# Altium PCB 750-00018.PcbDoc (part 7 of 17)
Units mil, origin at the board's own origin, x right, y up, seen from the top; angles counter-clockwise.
Board outline 7086.64 x 6299.21 mil, 8 copper layers (Top Layer, L2, L3, L4, L5, L6, L7, Bottom Layer), stack 60.6 mil thick; 1356 components, 1054 nets, 4851 pads, 4296 vias.
Unrouted connection lines stored in the file: 12.
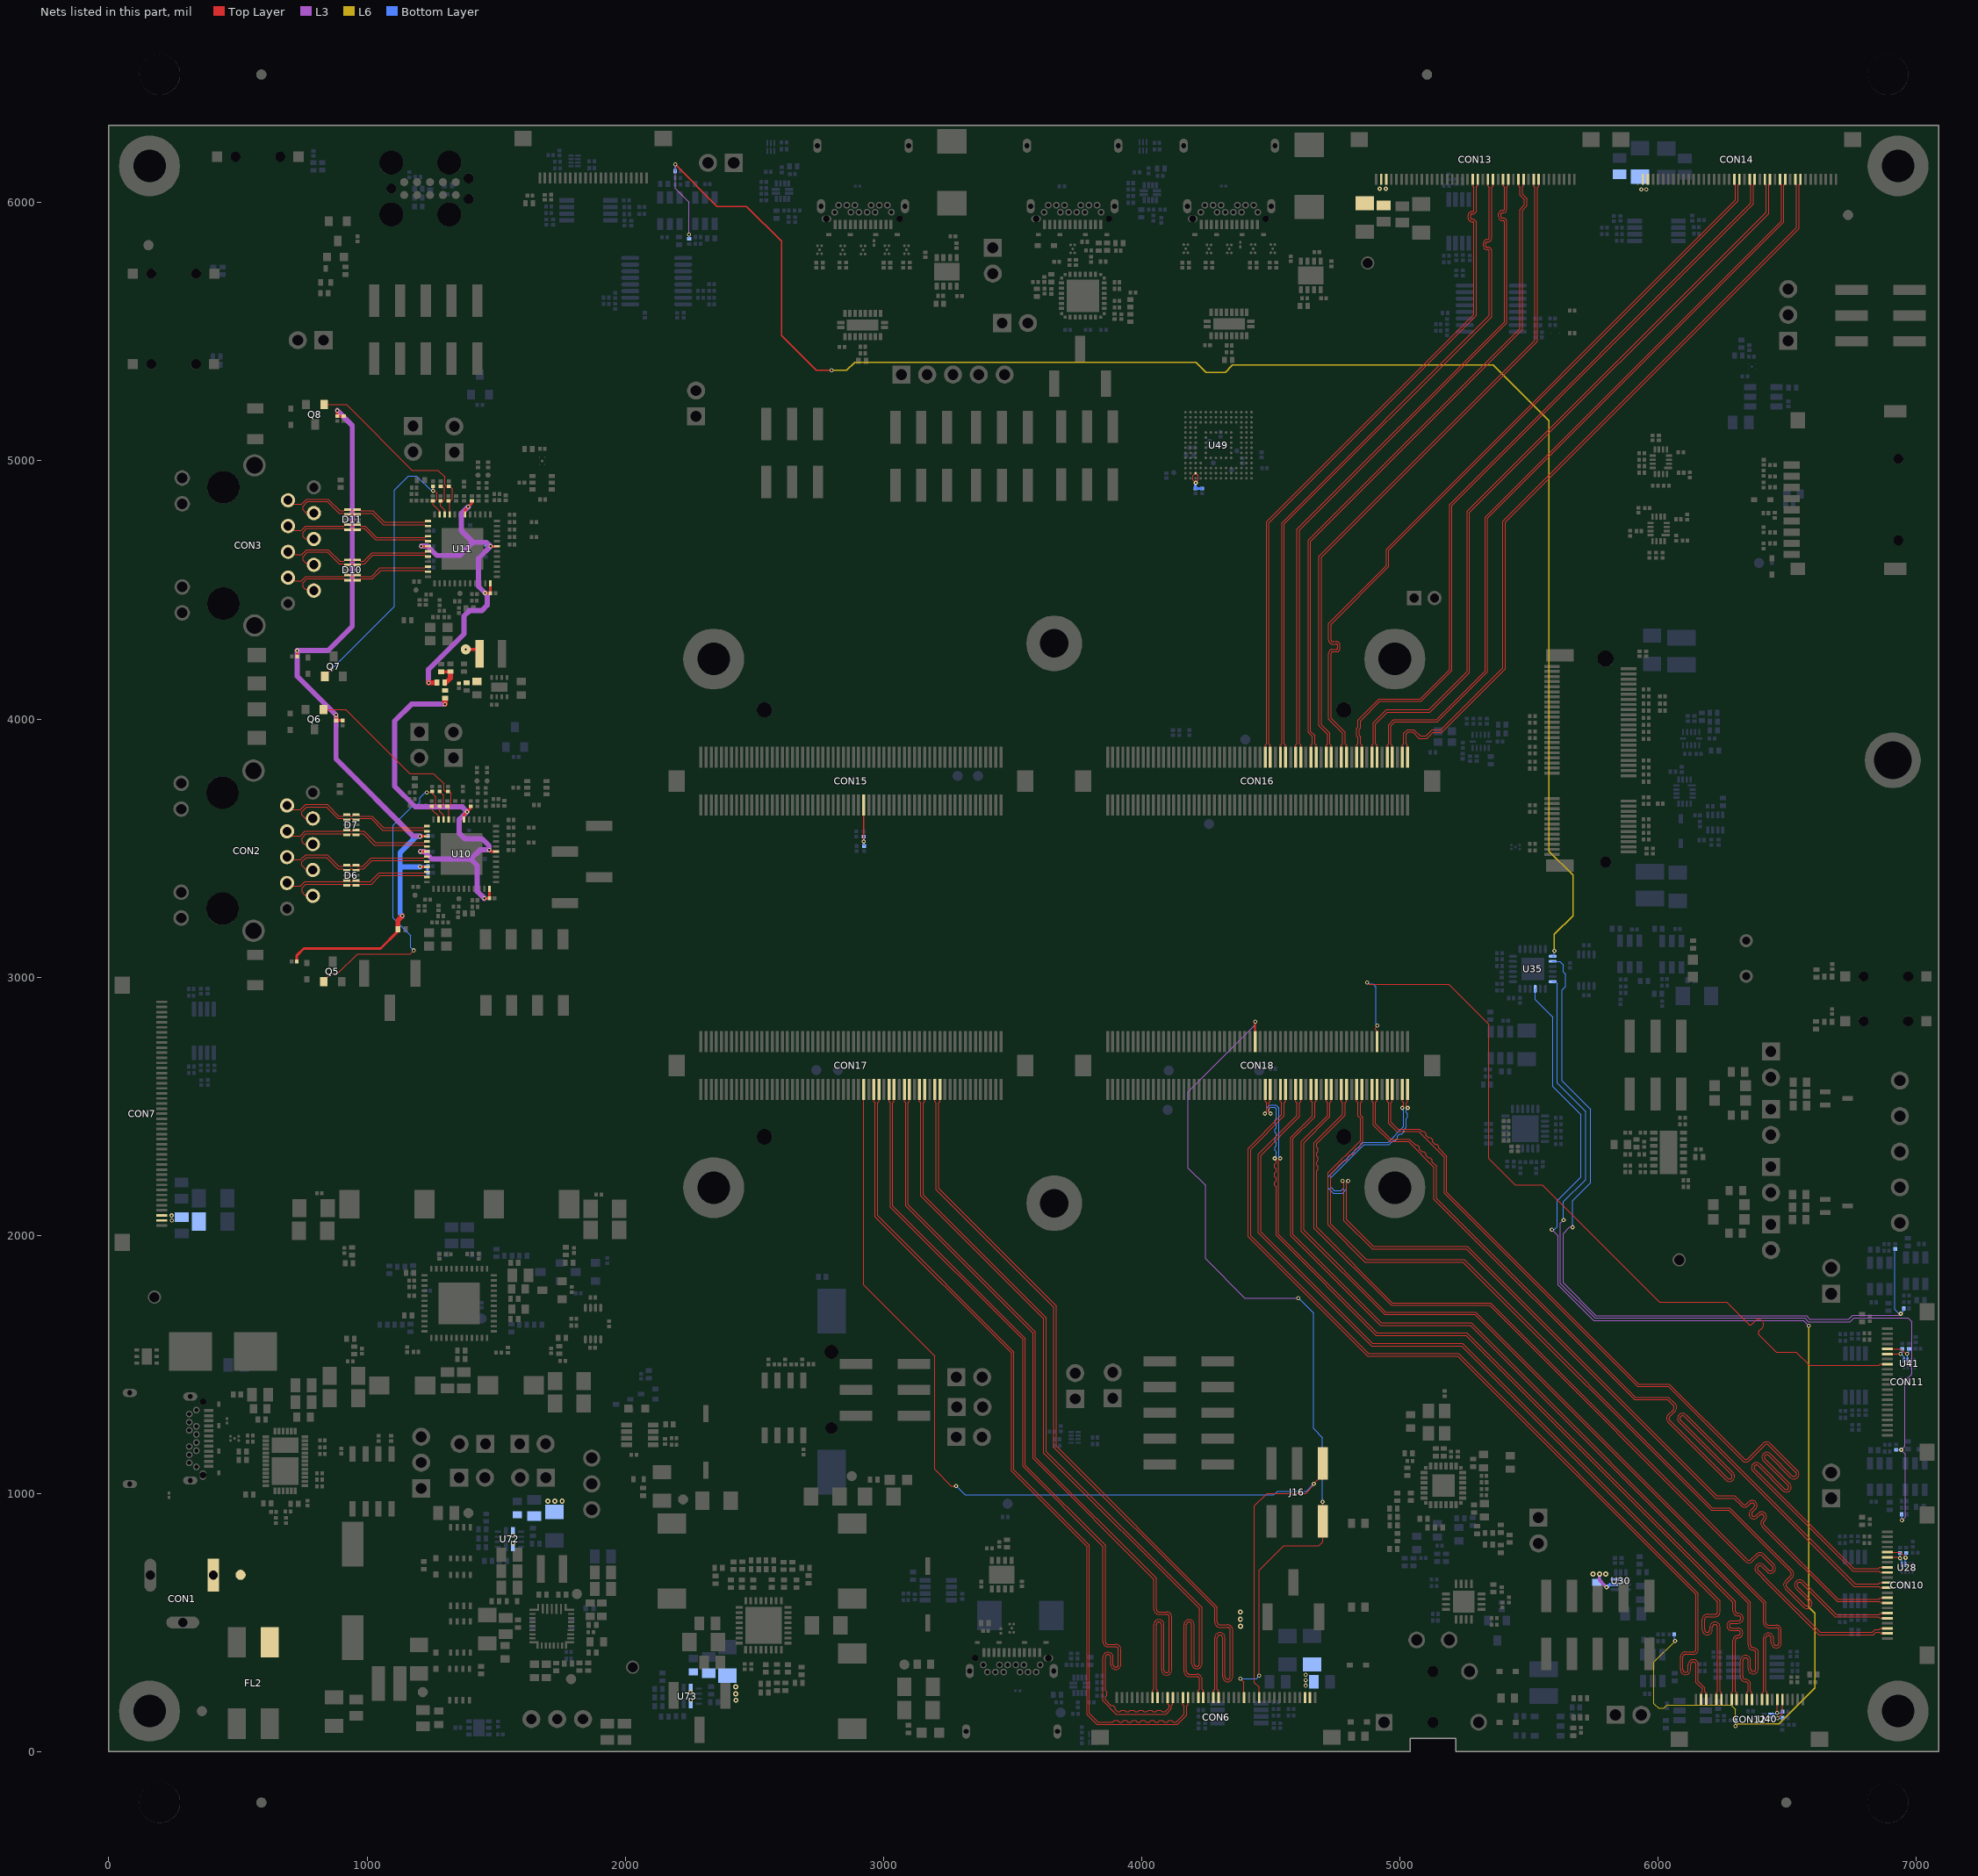
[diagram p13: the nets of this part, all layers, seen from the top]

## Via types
v1: diameter 16, hole 8, Top Layer to Bottom Layer, tented both sides, 3994 vias
v2: diameter 20, hole 10, Top Layer to Bottom Layer, tented both sides, 266 vias
v3: diameter 14, hole 7.87, Top Layer to Bottom Layer, tented both sides, 24 vias
v4: diameter 22, hole 12, Top Layer to Bottom Layer, tented both sides, 8 vias
v5: diameter 24, hole 12, Top Layer to Bottom Layer, tented both sides, 4 vias

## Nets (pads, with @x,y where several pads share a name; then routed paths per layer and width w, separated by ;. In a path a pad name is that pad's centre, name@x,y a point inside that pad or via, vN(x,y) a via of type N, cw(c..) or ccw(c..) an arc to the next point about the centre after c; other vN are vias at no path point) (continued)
CSI_B_DATA3_P: CON11.15 CON18.14 | length 3264
  Top Layer w4: v1(4873.09,2979.63) 4879.51,2973.2 5189.03,2973.2 5344.29,2817.94 5344.29,2297.3 5446.86,2194.73 5551.76,2194.73 6005.26,1741.23 6264.91,1741.23 6345.25,1660.89 6350.02,1656.11 ccw(c6356.74,1662.83) 6363.46,1656.11 6376.06,1668.72 cw(c6389.5,1655.28) 6402.93,1668.72 cw(c6389.5,1655.28) 6402.93,1641.85 6390.33,1629.24 ccw(c6397.05,1622.53) 6390.33,1615.81 6429.57,1576.57 6457.54,1548.6 6534.34,1548.6 6586.88,1496.07 6855.69,1496.07 6860.79,1501.16 CON11.15@6887.83,1501.16 ; CON18.14@4911.42,2750.44 4911.42,2792.84 4906.13,2798.12 4906.13,2803.74 4912.54,2810.15 v1(4912.54,2812.51)
  Bottom Layer w4: v1(4873.09,2979.63) 4879.34,2973.38 4894.84,2973.38 4906.74,2961.48 4906.74,2818.32 v1(4912.54,2812.51)
"CSI_B_GPIO0 / PWR": CON11.17 R386.1 U41.5 | length 106
  Top Layer w4: CON11.17@6887.83,1540.53 6888.17,1540.87 6888.4,1540.64 v1(6938.76,1540.64)
  Bottom Layer w4: R386.1@6946.07,1560.95 6946.87,1560.16 6946.87,1548.75 v1(6938.76,1540.64) 6941.04,1540.64 6952.6,1529.08 U41.5@6952.6,1516.85
"CSI_B_GPIO1 / RST": CON11.18 R385.1 U41.6 | length 135.2
  Top Layer w4: CON11.18@6887.83,1560.22 6941.02,1560.22 6961.36,1539.87 6963.44,1539.87 v1(6964.47,1540.9)
  Bottom Layer w4: U41.6@6966.38,1516.85 6966.38,1539 v1(6964.47,1540.9) 6967.41,1540.9 6970.53,1544.02 6970.53,1559.65 R385.1@6971.83,1560.95
CSI_C_CLOCK_N: CON10.8 CON18.1 | length 3659.9
  Top Layer w4: v1(4777.71,2211.06) 4783.92,2204.86 4783.92,2056.77 4892.85,1947.84 5257.03,1947.84 6223.04,981.83 6292.87,981.83 6317.38,957.32 6322.14,952.56 ccw(c6335.59,965.98) 6349.02,952.55 6357.42,960.95 cw(c6364.14,954.23) 6370.86,960.95 cw(c6364.14,954.23) 6370.86,947.51 ; CON18.1@5029.53,2565.4 5029.53,2517.05 5024.44,2511.96 5024.44,2500.35 v1(5030.67,2494.12) ; 6370.84,947.49 6357.71,934.37 ccw(c6371.15,920.93) 6357.71,907.5 ccw(c6371.15,920.93) 6383.03,906.1 6383.19,906.1 6394.3,917.21 cw(c6401.01,910.49) 6407.73,917.21 cw(c6401.01,910.49) 6407.73,903.77 6402.76,898.81 ccw(c6416.2,885.37) 6402.78,871.92 6424.42,850.29 6693.22,581.48 6856.52,581.48 6861.62,576.39 CON10.8@6887.83,576.39
  Bottom Layer w4: v1(4777.71,2211.06) 4783.87,2204.9 4783.87,2183.68 4773.33,2173.14 4745.67,2173.14 4731.88,2186.93 4731.88,2222.2 4861.39,2351.71 4958.63,2351.71 4974.97,2368.05 4982.75,2368.05 4991.23,2376.53 4991.23,2384.31 4999.72,2392.8 5007.5,2392.8 5015.98,2401.28 5015.98,2409.06 5024.47,2417.55 5024.47,2452.92 5029.97,2458.43 5029.97,2470.43 5024.47,2475.93 5024.47,2487.93 v1(5030.67,2494.12)
CSI_C_CLOCK_P: CON10.9 CON18.3 | length 3661.8
  Top Layer w4: v1(4799.53,2211.06) 4793.42,2204.95 4793.42,2060.71 4896.78,1957.34 5260.97,1957.34 6226.98,991.33 6296.8,991.33 6324.1,964.04 6328.87,959.26 ccw(c6335.59,965.98) 6342.31,959.26 6350.71,967.66 cw(c6364.14,954.23) 6377.58,967.66 cw(c6364.14,954.23) 6378.97,942.35 6378.97,942.19 6364.43,927.65 ccw(c6371.15,920.93) 6364.43,914.21 ccw(c6371.15,920.93) 6377.87,914.21 ; v1(5008.85,2494.12) 5014.94,2500.21 5014.94,2513.4 5009.84,2518.49 CON18.3@5009.84,2565.4 ; 6377.89,914.23 6387.58,923.93 cw(c6401.01,910.49) 6414.45,923.93 cw(c6401.01,910.49) 6414.45,897.06 ; 6414.45,897.06 6409.48,892.09 ccw(c6416.2,885.37) 6409.48,878.65 6431.13,857 6697.15,590.98 6855.27,590.98 6860.36,596.08 CON10.9@6887.83,596.08
  Bottom Layer w4: v1(4799.53,2211.06) 4793.37,2204.9 4793.37,2179.75 4777.26,2163.64 4741.73,2163.64 4722.38,2183 4722.38,2226.13 4857.45,2361.21 4954.69,2361.21 5014.97,2421.48 5014.97,2488 v1(5008.85,2494.12)
CSI_C_DATA0_N: CON10.2 CON18.27 | length 3662
  Top Layer w4: CON18.27@4773.62,2565.4 4773.62,2518.48 4778.72,2513.39 4778.72,2469.6 4667.58,2358.46 4667.58,2027.99 4966.68,1728.89 5347.21,1728.89 6333.33,742.77 6338.09,738 6338.14,737.96 ccw(c6352.06,751.96) 6366,737.96 6387.26,759.23 cw(c6394.49,751.96) 6401.71,759.23 6442.73,718.22 cw(c6435.48,710.97) 6442.73,703.72 cw(c6435.48,710.97) 6428.23,703.72 6408.46,723.5 ccw(c6394.49,709.53) 6380.53,695.57 6425.76,650.33 6434.05,642.04 6623.21,452.88 6833.36,452.88 6843.85,463.37 6857.27,463.37 6862.37,458.28 CON10.2@6887.83,458.28
CSI_C_DATA0_P: CON10.3 CON18.25 | length 3659.9
  Top Layer w4: CON18.25@4793.31,2565.4 4793.31,2518.17 4788.22,2513.08 4788.22,2465.66 4677.08,2354.53 4677.08,2342.53 4682.58,2337.03 4682.58,2325.03 4677.08,2319.52 4677.08,2307.53 4682.58,2302.02 4682.58,2290.02 4677.08,2284.52 4677.08,2272.52 4682.58,2267.02 4682.58,2255.02 4677.08,2249.52 4677.08,2031.93 4970.62,1738.39 5351.14,1738.39 6340.04,749.48 6344.82,744.7 ccw(c6352.06,751.96) 6359.29,744.69 6380.56,765.96 cw(c6394.49,751.96) 6408.42,765.96 6449.45,724.93 cw(c6435.48,710.97) 6449.45,697 cw(c6435.48,710.97) 6421.52,697 6401.74,716.78 ccw(c6394.49,709.53) 6387.24,702.29 6437.39,652.14 6440.77,648.76 6627.14,462.38 6829.42,462.38 6839.91,472.87 6856.55,472.87 6861.64,477.97 CON10.3@6887.83,477.97
CSI_C_DATA1_N: CON10.5 CON18.21 | length 3662
  Top Layer w4: CON18.21@4832.68,2565.4 4832.68,2519.15 4837.77,2514.06 4837.77,2462.69 4846.96,2453.5 4846.96,2367.02 4722.38,2242.44 4722.38,2039.98 4865.47,1896.89 5244.33,1896.89 6206.24,934.98 6273.36,934.98 6507.81,700.53 6512.56,695.78 ; 6512.58,695.76 cw(c6505.33,688.51) 6512.6,681.28 6491.34,660.03 ccw(c6505.33,646.09) 6491.31,632.18 6562.62,560.87 ccw(c6576.59,574.83) 6590.55,560.87 ccw(c6576.59,574.83) 6590.55,588.8 6540.51,638.84 cw(c6547.76,646.09) 6555.01,653.33 6644.79,563.55 6648.18,560.17 6685.91,522.43 6854,522.43 6859.09,517.34 CON10.5@6887.83,517.34
CSI_C_DATA1_P: CON10.6 CON18.19 | length 3659.9
  Top Layer w4: 4823.23,2322.07 4814.75,2313.59 4806.97,2313.59 4798.48,2305.1 4798.48,2297.33 4790,2288.84 4782.22,2288.84 4731.88,2238.5 4731.88,2043.92 4869.41,1906.39 5248.27,1906.39 6210.18,944.48 6277.29,944.48 6514.52,707.25 6519.29,702.48 ; 4823.23,2322.08 4823.23,2329.85 4831.71,2338.34 4839.49,2338.34 4847.98,2346.82 ; 4847.98,2346.82 4847.98,2354.6 4856.46,2363.09 4856.46,2457.43 4847.27,2466.63 4847.27,2513.56 4852.36,2518.65 CON18.19@4852.36,2565.4 ; 6519.32,702.45 cw(c6505.33,688.51) 6519.32,674.57 6498.07,653.32 ccw(c6505.33,646.09) 6498.06,638.87 6569.34,567.58 ccw(c6576.59,574.83) 6583.83,567.58 ccw(c6576.59,574.83) 6583.83,582.08 6533.79,632.12 cw(c6547.76,646.09) 6561.72,660.05 6637.37,584.4 6654.89,566.88 6689.85,531.93 6854.75,531.93 6859.84,537.02 CON10.6@6887.83,537.02
CSI_C_DATA2_N: CON10.11 CON18.15 | length 3662
  Top Layer w4: CON18.15@4891.73,2565.4 4891.73,2519.12 4896.83,2514.03 4896.83,2427.49 4960.94,2363.37 5033.04,2363.37 5132.43,2263.98 5132.43,2139.34 5907.9,1363.87 6035.78,1363.87 6054.48,1345.16 6059.24,1340.41 ; 6059.26,1340.39 cw(c6052.01,1333.14) 6059.28,1325.91 6038.02,1304.65 ccw(c6052.01,1290.72) 6038.02,1276.78 6262.3,1052.49 ccw(c6276.27,1066.46) 6290.23,1052.49 ccw(c6276.27,1066.46) 6290.23,1080.42 6087.19,1283.47 cw(c6094.44,1290.72) 6101.68,1297.96 6370.29,1029.35 6759.11,640.54 6855.13,640.54 6860.23,635.45 CON10.11@6887.83,635.45
CSI_C_DATA2_P: CON10.12 CON18.13 | length 3659.9
  Top Layer w4: CON18.13@4911.42,2565.4 4911.42,2520.14 4906.33,2515.04 4906.33,2431.43 4964.88,2372.87 5036.97,2372.87 5059.86,2349.98 5067.64,2349.98 5076.13,2341.5 5076.13,2333.72 5084.61,2325.23 5092.39,2325.23 5100.88,2316.75 5100.88,2308.97 5109.36,2300.49 5117.14,2300.49 5125.62,2292 5125.62,2284.22 5141.93,2267.92 5141.93,2143.27 5911.83,1373.37 6039.71,1373.37 6061.2,1351.88 6065.97,1347.11 cw(c6052.01,1333.14) 6066,1319.2 6044.74,1297.94 ccw(c6052.01,1290.72) 6044.74,1283.49 6269.02,1059.21 ccw(c6276.27,1066.46) 6283.52,1059.21 ccw(c6276.27,1066.46) 6283.52,1073.7 6080.47,1276.75 cw(c6094.44,1290.72) 6108.4,1304.68 6377.01,1036.07 6763.04,650.04 6854.34,650.04 6859.44,655.13 CON10.12@6887.83,655.13
CSI_C_DATA3_N: CON10.14 CON18.9 | length 3661.8
  Top Layer w4: CON18.9@4950.79,2565.4 4950.79,2518.71 4955.88,2513.61 4955.88,2434.25 4987.83,2402.3 5072.34,2402.3 5171.88,2302.76 5171.88,2162.82 5919.99,1414.71 6039.47,1414.71 6321.94,1132.24 6326.71,1127.48 6326.76,1127.43 ccw(c6340.15,1140.91) 6326.93,1127.25 ccw(c6340.15,1140.9) 6353.58,1127.46 6414.05,1187.93 cw(c6420.76,1181.21) 6427.47,1187.93 6533.01,1082.39 cw(c6526.29,1075.67) 6519.58,1068.96 6434.2,1154.34 ccw(c6420.76,1140.9) 6407.33,1127.47 6503.36,1031.44 cw(c6496.64,1024.72) 6503.36,1018 cw(c6496.64,1024.72) 6489.92,1018 6393.88,1114.04 ccw(c6380.46,1100.6) 6367.01,1114.03 ccw(c6380.46,1100.6) 6367.02,1087.16 6477.9,976.28 6754.59,699.59 6855.19,699.59 6860.29,694.5 CON10.14@6887.83,694.5
CSI_C_DATA3_P: CON10.15 CON18.7 | length 3659.7
  Top Layer w4: CON18.7@4970.47,2565.4 4970.47,2518.5 4965.38,2513.4 4965.38,2438.19 4991.76,2411.8 5076.28,2411.8 5084.76,2403.32 5092.54,2403.32 5101.03,2394.84 5101.03,2387.06 5109.51,2378.57 5117.29,2378.57 5125.78,2370.09 5125.78,2362.31 5134.26,2353.82 5142.04,2353.82 5150.53,2345.34 5150.53,2337.56 5181.38,2306.7 5181.38,2166.76 5923.92,1424.21 6043.4,1424.21 6328.66,1138.96 6333.44,1134.18 ; 6333.46,1134.16 ccw(c6340.15,1140.91) 6333.54,1134.08 ccw(c6340.15,1140.9) 6346.87,1134.18 6407.33,1194.65 cw(c6420.76,1181.21) 6434.19,1194.65 6539.73,1089.11 cw(c6526.29,1075.67) 6512.86,1062.24 6427.48,1147.62 ccw(c6420.76,1140.9) 6414.04,1134.19 6510.08,1038.15 cw(c6496.64,1024.72) 6510.08,1011.28 cw(c6496.64,1024.72) 6483.21,1011.28 6387.17,1107.32 ccw(c6380.46,1100.6) 6373.74,1107.31 ccw(c6380.46,1100.6) 6373.74,1093.88 6484.62,983 6758.52,709.09 6853.56,709.09 6858.65,714.19 CON10.15@6887.83,714.19
"CSI_C_GPIO0 / PWR": CON10.17 R360.1 U28.5 | length 97.9
  Top Layer w4: CON10.17@6887.83,753.56 6932.8,753.56 v1(6936.76,749.6)
  Bottom Layer w4: R360.1@6936.52,770.29 6936.52,749.84 v1(6936.76,749.6) 6944.03,742.33 U28.5@6944.03,726.08
"CSI_C_GPIO1 / RST": CON10.18 R359.1 U28.6 | length 125.5
  Top Layer w4: CON10.18@6887.83,773.24 6936.88,773.24 v1(6958.5,751.62)
  Bottom Layer w4: U28.6@6957.81,726.08 6957.81,750.93 v1(6958.5,751.62) 6961.41,754.53 R359.1@6961.41,770.45
CSI_D_CLOCK_N: CON12.8 CON18.55 | length 3532.1
  Top Layer w4: CON18.55@4498.03,2565.4 4498.03,2518.99 4492.94,2513.9 4492.94,2478.07 v1(4499.23,2471.78) ; v1(4515.23,2298.56) 4520.64,2293.15 4520.64,2281.15 4515.14,2275.65 4515.14,2263.65 4520.64,2258.15 4520.64,2246.15 4515.14,2240.65 4515.14,2228.65 4520.64,2223.15 4520.64,2211.15 4515.14,2205.64 4515.14,2193.65 4520.64,2188.14 4520.64,1999.61 4907.46,1612.79 5255.9,1612.79 6289.8,578.89 6289.8,552.25 6289.8,545.5 ccw(c6308.8,545.5) 6308.8,526.5 6310.45,526.5 cw(c6310.45,517) 6310.45,507.5 6285.04,507.5 ccw(c6285.04,488.5) 6285.04,469.5 6308.8,469.5 cw(c6308.8,460) 6308.8,450.5 ccw(c6308.8,431.5) 6289.8,431.5 6289.8,383.66 6289.8,234.73 6284.4,229.33 CON12.8@6284.4,202.02
  Bottom Layer w4: v1(4499.23,2471.78) 4493.07,2477.94 4493.07,2489.88 4499.15,2495.96 4514.97,2495.96 4521.81,2489.11 4521.81,2451.59 4516.31,2446.09 4516.31,2434.09 4521.81,2428.59 4521.81,2416.59 4516.31,2411.09 4516.31,2399.09 4521.81,2393.59 4521.81,2381.59 4516.31,2376.09 4516.31,2364.09 4521.81,2358.58 4521.81,2346.58 4516.31,2341.08 4516.31,2329.08 4521.81,2323.58 4521.81,2305.15 v1(4515.23,2298.56)
CSI_D_CLOCK_P: CON12.9 CON18.57 | length 3531.6
  Top Layer w4: v1(4477.42,2471.78) 4483.44,2477.8 4483.44,2514.2 4478.35,2519.29 CON18.57@4478.35,2565.4 ; v1(4537.05,2298.56) 4530.14,2291.66 4530.14,2003.55 4911.4,1622.29 5259.83,1622.29 6299.3,582.83 6299.3,552.25 6299.3,545.5 ccw(c6308.8,545.5) 6308.8,536 6310.45,536 cw(c6310.45,517) 6310.45,498 6285.04,498 ccw(c6285.04,488.5) 6285.04,479 6308.8,479 cw(c6308.8,460) 6308.8,441 ccw(c6308.8,431.5) 6299.3,431.5 6299.3,383.66 6299.3,233.98 6304.08,229.2 CON12.9@6304.08,202.02
  Bottom Layer w4: v1(4477.42,2471.78) 4483.57,2477.94 4483.57,2493.82 4495.21,2505.46 4518.9,2505.46 4531.31,2493.05 4531.31,2304.3 v1(4537.05,2298.56)
CSI_D_DATA0_N: CON12.2 CON18.51 | length 3533
  Top Layer w4: CON18.51@4537.4,2565.4 4537.4,2517.95 4542.49,2512.86 4542.49,2467.38 4412.42,2337.31 4412.42,1994.34 4874.22,1532.54 5222.66,1532.54 6146.32,608.87 6146.32,403.92 6146.32,397.17 cw(c6136.07,397.17) 6136.07,386.92 6106.07,386.92 ccw(c6106.07,367.17) 6086.32,367.17 6086.32,318.44 ccw(c6106.07,318.44) 6125.82,318.44 6125.82,337.17 cw(c6136.07,337.17) 6146.32,337.17 6146.32,272.91 6146.32,268.28 6171.38,243.22 6171.38,234.33 6166.29,229.23 CON12.2@6166.29,202.02
CSI_D_DATA0_P: CON12.3 CON18.49 | length 3533
  Top Layer w4: CON18.49@4557.09,2565.4 4557.09,2518.39 4551.99,2513.3 4551.99,2463.45 4421.92,2333.37 4421.92,1998.27 4878.15,1542.04 5226.59,1542.04 6155.82,612.81 6155.82,403.92 6155.82,397.17 cw(c6136.07,397.17) 6136.07,377.42 6106.07,377.42 ccw(c6106.07,367.17) 6095.82,367.17 6095.82,318.44 ccw(c6106.07,318.44) 6116.32,318.44 6116.32,337.17 cw(c6136.07,337.17) 6155.82,337.17 6155.82,272.91 6155.82,272.21 6180.88,247.15 6180.88,234.08 6185.97,228.98 CON12.3@6185.97,202.02
CSI_D_DATA1_N: CON12.5 CON18.45 | length 3532.1
  Top Layer w4: CON18.45@4596.46,2565.4 4596.46,2518.98 4601.55,2513.89 4601.55,2463.86 4451.45,2313.75 4451.45,2010.5 4890.38,1571.57 5238.82,1571.57 6230.43,579.95 6230.43,549.39 6230.43,542.64 cw(c6220.18,542.64) 6220.18,532.39 6190.18,532.39 ccw(c6190.18,512.64) 6170.43,512.64 6170.43,472.65 ccw(c6190.18,472.65) 6209.93,472.65 6209.93,482.64 cw(c6220.18,482.64) 6230.43,482.64 6230.43,396.74 6230.43,232.87 6225.34,227.77 CON12.5@6225.34,202.02
CSI_D_DATA1_P: CON12.6 CON18.43 | length 3532.1
  Top Layer w4: CON18.43@4616.14,2565.4 4616.14,2518.39 4611.05,2513.29 4611.05,2459.92 4460.95,2309.82 4460.95,2014.44 4894.32,1581.07 5242.76,1581.07 6239.93,583.89 6239.93,549.39 6239.93,542.64 cw(c6220.18,542.64) 6220.18,522.89 6190.18,522.89 ccw(c6190.18,512.64) 6179.93,512.64 6179.93,472.65 ccw(c6190.18,472.65) 6200.43,472.65 6200.43,482.64 cw(c6220.18,482.64) 6239.93,482.64 6239.93,396.74 6239.93,233.15 6245.03,228.06 CON12.6@6245.03,202.02
CSI_D_DATA2_N: CON12.11 CON18.39 | length 3532.1
  Top Layer w4: CON18.39@4655.51,2565.4 4655.51,2519.56 4660.6,2514.47 4660.6,2463.19 4577.05,2379.64 4577.05,1998.75 4923.73,1652.07 5272.17,1652.07 6348.54,575.69 6348.54,419.88 6348.54,413.13 ccw(c6368.29,413.13) 6368.29,393.38 cw(c6368.29,383.13) 6378.54,383.13 6378.54,321.38 cw(c6368.29,321.38) 6358.04,321.38 6358.04,353.13 ccw(c6338.29,353.13) 6318.54,353.13 6318.54,290.8 ccw(c6338.29,290.8) 6338.29,271.05 cw(c6338.29,260.8) 6348.54,260.8 6348.54,254.05 6348.54,235.5 6343.45,230.41 CON12.11@6343.45,202.02
CSI_D_DATA2_P: CON12.12 CON18.37 | length 3532.1
  Top Layer w4: CON18.37@4675.2,2565.4 4675.2,2519.8 4670.1,2514.71 4670.1,2459.26 4586.55,2375.7 4586.55,2002.69 4927.67,1661.57 5276.1,1661.57 6358.04,579.63 6358.04,419.88 6358.04,413.13 ccw(c6368.29,413.13) 6368.29,402.88 cw(c6368.29,383.13) 6388.04,383.13 6388.04,321.38 cw(c6368.29,321.38) 6348.54,321.38 6348.54,353.13 ccw(c6338.29,353.13) 6328.04,353.13 6328.04,290.8 ccw(c6338.29,290.8) 6338.29,280.55 cw(c6338.29,260.8) 6358.04,260.8 6358.04,254.05 6358.04,235 6363.14,229.91 CON12.12@6363.14,202.02
CSI_D_DATA3_N: CON12.14 CON18.33 | length 3533
  Top Layer w4: CON18.33@4714.57,2565.4 4714.57,2518.25 4719.66,2513.16 4719.66,2464.66 4618.21,2363.21 4618.21,2015.8 4940.78,1693.23 5289.22,1693.23 6407.6,574.85 6407.6,507.2 6407.6,500.45 ccw(c6427.35,500.45) 6427.35,480.7 6457.35,480.7 cw(c6457.35,470.45) 6467.6,470.45 6467.6,422.1 cw(c6457.35,422.1) 6447.1,422.1 6447.1,440.45 ccw(c6427.35,440.45) 6407.6,440.45 6407.6,330.79 6407.6,234.28 6402.51,229.19 CON12.14@6402.51,202.02
CSI_D_DATA3_P: CON12.15 CON18.31 | length 3533
  Top Layer w4: CON18.31@4734.25,2565.4 4734.25,2518.62 4729.16,2513.52 4729.16,2460.73 4627.71,2359.28 4627.71,2019.74 4944.72,1702.73 5293.15,1702.73 6417.1,578.79 6417.1,507.2 6417.1,500.45 ccw(c6427.35,500.45) 6427.35,490.2 6457.35,490.2 cw(c6457.35,470.45) 6477.1,470.45 6477.1,422.1 cw(c6457.35,422.1) 6437.6,422.1 6437.6,440.45 ccw(c6427.35,440.45) 6417.1,440.45 6417.1,330.79 6417.1,235.15 6422.19,230.06 CON12.15@6422.19,202.02
"CSI_D_GPIO0 / PWR": CON12.17 R384.1 U40.5 | length 100.6
  Top Layer w4: v1(6461.18,150.34) 6461.56,150.72 CON12.17@6461.56,202.02
  Bottom Layer w4: U40.5@6437.04,147.25 6458.1,147.25 v1(6461.18,150.34) 6476.78,150.34 R384.1@6482.28,155.85
"CSI_D_GPIO1 / RST": CON12.18 R383.1 U40.6 | length 126.9
  Top Layer w4: v1(6463.16,129.84) 6481.25,147.93 CON12.18@6481.25,202.02
  Bottom Layer w4: U40.6@6437.04,133.47 6459.53,133.47 v1(6463.16,129.84) 6481.13,129.84 6481.21,129.77 R383.1@6482.28,130.84
CSI_HV: C292.2 C419.1 C420.1 R603.1 U30.5 U30.6 U72.1 U72.8 | length 97.1
  L3 w12: v2(5772.95,688.34) 5772.95,664.85 v1(5800.27,637.53)
  Bottom Layer w12: v1(5800.27,637.53) 5802.32,637.53 5813.1,648.32 U30.5@5830.82,648.32
  other v1: 1564.85,807.65 1564.85,839.15
  other v2: 4382.85,485.73 4382.08,513.51 4381.88,541.3 5747.49,688.44 5796.93,688.34 1699.85,970.13 1727.64,970.13 1755.42,970.13
CSI_PWR_control_A: R577.1 R583.1 U35.7 | length 6541.2
  Top Layer w5: v1(2193.81,6147.64) 2355.8,5985.66 2470.01,5985.66 2605.64,5850.03 2605.64,5484.79 2739.35,5351.08 v1(2799.29,5351.08)
  L3 w4: v1(2193.81,6147.64) 2193.81,6054.44 2246.62,6001.64 v1(2246.62,5876.21)
  L6 w5: v1(2799.29,5351.08) 2857.58,5351.08 2888.5,5382 4210.17,5382 4249.4,5342.77 4323.96,5342.77 4352.01,5370.83 5361.18,5370.83 5576.77,5155.24 5576.77,3488.38 5669.75,3395.4 5669.75,3238.43 5598.01,3166.69 v1(5598.01,3101.87)
  Bottom Layer w4: v1(2246.62,5876.21) 2246.62,5860.39 R577.1@2247.45,5859.56 ; U35.7@5591.4,3081.08 5595.87,3081.08 5598.01,3083.22 v1(5598.01,3101.87)
  Bottom Layer w5: R583.1@2193.52,6121.5 2193.52,6147.36 v1(2193.81,6147.64)
CSI_PWR_control_B: R590.1 R595.1 U35.8 | length 3048.7
  L3 w4: v1(5668.72,2031.55) 5656.89,2031.55 5632.67,2007.33 5632.67,1815.85 5759.69,1688.83 6574.09,1688.83 6587.2,1675.72 6738.93,1675.72 6753.63,1690.41 6933.23,1690.41 v1(6939.5,1696.68)
  Bottom Layer w4: U35.8@5591.4,3061.4 5619.14,3061.4 5632.64,3047.89 5632.64,3019.57 5640.82,3011.39 5640.82,2963.61 5628.31,2951.1 5628.31,2598.76 5738.99,2488.08 5738.99,2203.99 5668.72,2133.72 v1(5668.72,2031.55) ; R590.1@6918.63,1947.32 6915.93,1944.62 6915.93,1713.22 6932.46,1696.68 v1(6939.5,1696.68) 6951.69,1708.88 R595.1@6951.69,1716.89
CSI_PWR_control_C: R579.1 R585.1 U35.12 | length 3545.2
  L3 w4: v1(5633.95,2059.7) 5622.02,2047.77 5622.02,1813.18 5755.47,1679.73 6568.23,1679.73 6582.19,1665.76 6742.56,1665.76 6758.05,1681.25 6966.88,1681.25 6983.11,1665.02 6983.11,1462.57 6956.13,1435.59 6956.13,1184.32 v1(6941.18,1169.37) 6956.98,1153.57 6956.98,908.8 v1(6944.43,896.24)
  Bottom Layer w4: U35.12@5591.4,2982.66 5601.24,2982.66 5608.69,2975.2 5608.69,2589.48 5719.13,2479.03 5719.13,2216.6 5633.95,2131.41 v1(5633.95,2059.7) ; R579.1@6921.76,1169.89 6940.66,1169.89 v1(6941.18,1169.37) ; R585.1@6943.48,919.84 6943.48,897.19 v1(6944.43,896.24)
CSI_PWR_control_D: R589.1 R596.1 U35.15 | length 4826.2
  L3 w4: v1(5588.34,2022.23) 5612.6,1997.97 5612.6,1807.08 5750.19,1669.49 6563.26,1669.49 v1(6583.06,1649.69)
  L6 w4: v1(6065.87,429.3) 5983.58,347.02 5983.58,186.42 6001.22,168.78 6022.67,168.78 6034.54,180.66 6283.26,180.66 6299.56,164.35 v1(6299.56,98.89)
  L6 w5: v1(6299.56,98.89) 6308.67,108 6467.92,108 6606.54,246.62 6606.54,535.96 6583.18,559.31 6583.06,559.43 v1(6583.06,1649.69)
  Bottom Layer w4: U35.15@5524.23,2954.86 5524.23,2912.52 5591.56,2845.19 5591.56,2577.02 5701.43,2467.15 5701.43,2226.53 5609.89,2134.99 5609.89,2034.29 5597.83,2022.23 v1(5588.34,2022.23) ; R589.1@6062.82,454.52 6062.82,432.35 v1(6065.87,429.3)
  Bottom Layer w5: v1(6299.56,98.89) R596.1@6299.55,121.02
DCJACK12V: CON1.1 FL2.1 TP8.1
DEBUG_EN: CON15.66 R221.1 R607.1 | length 178.3
  Top Layer w5: v1(2923.23,3525.94) CON15.66@2923.23,3666.88
  Bottom Layer w5: R607.1@2923.38,3544.75 2923.38,3526.09 v1(2923.23,3525.94) 2924.61,3524.56 R221.1@2924.61,3508
DP_HV: C217.1 C218.1 C381.1 C382.1 C383.1 C384.1 C385.1 C386.1 C421.1 C422.1 CON6.38 CON6.39 CON7.43 CON7.44 CON13.38 CON13.39 CON14.38 CON14.39 R605.1 U73.1 U73.8
  other v1: 2253.9,199.69 2253.9,231.19 4635.08,256.35 4634.87,277.3 4635.49,298.55 243.55,2057.47 243.2,2077.11 5934.69,6050.74 5954.02,6050.96 4921.72,6053.62 4945.38,6053.93
  other v2: 2428.47,199.73 2427.89,223.86 2428.2,251.48
"DSI_ A_BL_PWM / LVDS_A_BL_PWM / PWM_0": CON6.26 CON18.62 J16.5 | length 3396.8
  Top Layer w4: v1(4381.65,283.46) 4396.07,269.03 CON6.26@4396.07,209.68 ; v1(4455.29,294.78) 4455.29,702.84 4550.31,797.87 4686.27,797.87 4701.95,813.55 J16.5@4701.95,892.47 4701.95,966.37 v1(4700.58,967.74)
  Top Layer w6: CON18.62@4438.98,2750.44 v1@4438.98,2827.49
  L3 w4: v1(4439.84,2828.35) 4439.84,2816.43 4180.13,2556.73 4180.13,2259.79 4246.85,2193.08 4246.85,1909.36 4398.87,1757.34 v1(4606.37,1757.34)
  Bottom Layer w4: v1(4381.65,283.46) 4443.97,283.46 v1(4455.29,294.78) ; v1(4606.37,1757.34) 4608.07,1757.34 4665.61,1699.81 4665.61,1251.25 4700.58,1216.27 v1(4700.58,967.74)
"DSI_A_CLOCK_N / LVDS_A_CLK_N": CON6.8 CON17.39 | length 3249.9
  Top Layer w4: CON17.39@3080.71,2565.4 3080.71,2517.77 3085.65,2512.83 3085.65,2114.52 3578.75,1621.42 3578.75,1136.01 4046.83,667.93 4046.83,558.8 4046.83,552.05 ccw(c4066.58,552.05) 4066.58,532.3 4096.58,532.3 cw(c4096.58,522.05) 4106.83,522.05 4106.83,316.8 cw(c4096.58,316.8) 4086.33,316.8 4086.33,492.05 ccw(c4066.58,492.05) 4046.83,492.05 4046.83,290.39 4046.83,242.91 4041.74,237.82 CON6.8@4041.74,209.68
"DSI_A_CLOCK_P / LVDS_A_CLK_P": CON6.9 CON17.37 | length 3250
  Top Layer w4: CON17.37@3100.4,2565.4 3100.4,2518.01 3095.15,2512.76 3095.15,2118.46 3588.25,1625.36 3588.25,1139.95 4056.33,671.87 4056.33,558.8 4056.33,552.05 ccw(c4066.58,552.05) 4066.58,541.8 4096.58,541.8 cw(c4096.58,522.05) 4116.33,522.05 4116.33,316.8 cw(c4096.58,316.8) 4076.83,316.8 4076.83,492.05 ccw(c4066.58,492.05) 4056.33,492.05 4056.33,290.39 4056.33,242.66 4061.42,237.56 CON6.9@4061.43,209.68
"DSI_A_DATA0_N / LVDS_A_LANE0_N": CON6.20 CON17.27 | length 3250
  Top Layer w4: CON17.27@3198.82,2565.4 3198.82,2517.77 3204.05,2512.54 3204.05,2177.17 3659.58,1721.63 3659.58,1179.44 4283.05,555.97 4283.05,508.65 4283.05,501.9 ccw(c4302.8,501.9) 4302.8,482.15 4332.8,482.15 cw(c4332.8,471.9) 4343.05,471.9 4343.05,291.05 cw(c4332.8,291.05) 4322.55,291.05 4322.55,441.9 ccw(c4302.8,441.9) 4283.05,441.9 4283.05,263.28 4283.05,242.25 4277.96,237.16 CON6.20@4277.96,209.68
"DSI_A_DATA0_P / LVDS_A_LANE0_P": CON6.21 CON17.25 | length 3249.9
  Top Layer w4: CON17.25@3218.51,2565.4 3218.51,2518.01 3213.55,2513.05 3213.55,2181.1 3669.08,1725.57 3669.08,1183.37 4292.55,559.9 4292.55,508.65 4292.55,501.9 ccw(c4302.8,501.9) 4302.8,491.65 4332.8,491.65 cw(c4332.8,471.9) 4352.55,471.9 4352.55,291.05 cw(c4332.8,291.05) 4313.05,291.05 4313.05,441.9 ccw(c4302.8,441.9) 4292.55,441.9 4292.55,263.28 4292.55,242 4297.65,236.91 CON6.21@4297.65,209.68
"DSI_A_DATA1_N / LVDS_A_LANE1_N": CON6.17 CON17.33 | length 3250
  Top Layer w4: CON17.33@3139.77,2565.4 3139.77,2517.77 3144.84,2512.69 3144.84,2152.86 3621.07,1676.63 3621.07,1157.56 4224,554.63 4224,540.34 4224,341.07 cw(c4213.75,341.07) 4203.5,341.07 4203.5,491.91 ccw(c4183.75,491.91) 4164,491.91 4164,311.07 ccw(c4183.75,311.07) 4183.75,291.32 4213.75,291.32 cw(c4213.75,281.07) 4224,281.07 4224,274.32 4224,242.53 4218.91,237.44 CON6.17@4218.91,209.68
"DSI_A_DATA1_P / LVDS_A_LANE1_P": CON6.18 CON17.31 | length 3250
  Top Layer w4: CON17.31@3159.45,2565.4 3159.45,2518.01 3154.34,2512.9 3154.34,2156.79 3630.57,1680.57 3630.57,1161.5 4233.5,558.57 4233.5,540.34 4233.5,341.07 cw(c4213.75,341.07) 4194,341.07 4194,491.91 ccw(c4183.75,491.91) 4173.5,491.91 4173.5,311.07 ccw(c4183.75,311.07) 4183.75,300.82 4213.75,300.82 cw(c4213.75,281.07) 4233.5,281.07 4233.5,274.32 4233.5,242.61 4238.59,237.52 CON6.18@4238.59,209.68
"DSI_A_DATA2_N / LVDS_A_LANE2_N": CON6.14 CON17.49 | length 3250.4
  Top Layer w4: CON17.49@2982.29,2565.4 2982.29,2518.01 2977.14,2512.86 2977.14,2076.01 3505.11,1548.04 3505.11,1091.72 3797.84,798.99 3797.84,147.93 3830.34,115.43 3889.31,115.43 3894.81,120.93 3906.81,120.93 3912.32,115.43 3924.32,115.43 3929.82,120.93 3941.82,120.93 3947.32,115.43 3959.32,115.43 3964.82,120.93 3976.82,120.93 3982.32,115.43 3994.32,115.43 3999.82,120.93 4011.82,120.93 4017.32,115.43 4029.32,115.43 4034.82,120.93 4046.82,120.93 4052.32,115.43 4064.32,115.43 4069.82,120.93 4081.82,120.93 4087.32,115.43 4099.32,115.43 4104.82,120.93 4116.82,120.93 4122.32,115.43 4134.32,115.43 4164.94,146.05 4164.94,177.87 4159.85,182.97 CON6.14@4159.85,209.68
"DSI_A_DATA2_P / LVDS_A_LANE2_P": CON6.15 CON17.51 | length 3250
  Top Layer w4: CON17.51@2962.6,2565.4 2962.6,2517.77 2967.64,2512.73 2967.64,2072.07 3495.61,1544.11 3495.61,1087.79 3788.34,795.05 3788.34,143.99 3826.41,105.93 3874.1,105.93 4138.26,105.93 4174.44,142.11 4174.44,177.76 4179.54,182.85 CON6.15@4179.54,209.68
"DSI_A_DATA3_N / LVDS_A_LANE3_N": CON6.11 CON17.43 | length 3250
  Top Layer w4: CON17.43@3041.34,2565.4 3041.34,2518.01 3036.16,2512.82 3036.16,2113.33 3210.54,1938.94 3549.11,1600.37 3549.11,1109.47 3859.22,799.37 3859.22,432.78 3859.22,426.03 ccw(c3869.47,426.03) 3869.47,415.78 3899.47,415.78 cw(c3899.47,396.03) 3919.22,396.03 3919.22,338 cw(c3899.47,338) 3879.72,338 3879.72,366.03 ccw(c3869.47,366.03) 3859.22,366.03 3859.22,311.62 3859.22,236.27 3864.72,230.77 3864.72,218.77 3859.22,213.27 3859.22,201.27 3880.63,179.86 3888.41,179.86 3896.9,171.37 3896.9,163.6 3905.38,155.11 3915.48,155.11 3920.98,160.61 3932.98,160.61 3938.48,155.11 3950.48,155.11 3955.98,160.61 3967.98,160.61 3973.48,155.11 3985.48,155.11 3990.98,160.61 4002.98,160.61 4008.48,155.11 4020.48,155.11 4025.98,160.61 4037.98,160.61 4043.49,155.11 4055.49,155.11 4060.99,160.61 4072.99,160.61 4078.49,155.11 4090.49,155.11 4105.89,170.51 4105.89,178.91 4100.8,184 CON6.11@4100.8,209.68
"DSI_A_DATA3_P / LVDS_A_LANE3_P": CON6.12 CON17.45 | length 3249.5
  Top Layer w4: CON17.45@3021.66,2565.4 3021.66,2517.77 3026.66,2512.77 3026.66,2109.39 3539.61,1596.44 3539.61,1105.54 3849.72,795.43 3849.72,432.78 3849.72,426.03 ccw(c3869.47,426.03) 3869.47,406.28 3899.47,406.28 cw(c3899.47,396.03) 3909.72,396.03 3909.72,338 cw(c3899.47,338) 3889.22,338 3889.22,366.03 ccw(c3869.47,366.03) 3849.72,366.03 3849.72,311.62 3849.72,197.34 3901.45,145.61 4094.42,145.61 4115.39,166.58 4115.39,179.88 4120.48,184.97 CON6.12@4120.48,209.68
DSI_A_TE: CON6.29 CON17.55 J16.6 | length 4225.1
  Top Layer w4: CON17.55@2923.23,2565.4 2923.23,1807.62 3198.34,1532.51 3198.34,1093.12 3261.83,1029.63 v1(3281.19,1029.63) ; CON6.29@4455.13,209.68 4455.13,250.25 4436.97,268.4 4436.97,952.13 4485.88,1001.04 4635.27,1001.04 4666.4,1032.17 v1(4666.4,1038.01) 4701.95,1073.56 J16.6@4701.95,1116.88
  Bottom Layer w4: v1(3281.19,1029.63) 3316.3,994.52 4510.97,994.52 4526.19,1009.74 4638.14,1009.74 v1(4666.4,1038.01)
eDP_A_AUX_N/LVDS_D_CLK_N: CON13.8 CON16.89 | length 2602.2
  Top Layer w4: CON16.89@4734.25,3851.92 4734.25,3898.95 4729.39,3903.82 4729.39,3944.17 4695.58,3977.97 4695.58,4626.04 5532.8,5463.26 5532.8,6060.01 5537.68,6064.89 CON13.8@5537.68,6089.26
eDP_A_AUX_P/LVDS_D_CLK_P: CON13.9 CON16.87 | length 2602.5
  Top Layer w4: CON16.87@4714.57,3851.92 4714.57,3898.75 4719.89,3904.07 4719.89,3940.23 4686.08,3974.04 4686.08,4629.98 5523.3,5467.2 5523.3,6059.69 5517.99,6065 CON13.9@5517.99,6089.26
eDP_A_LANE0_N/LVDS_D_LANE0_N: CON13.20 CON16.65 | length 2602.7
  Top Layer w4: CON16.65@4498.03,3851.92 4498.03,3898.95 4492.94,3904.05 4492.94,4759.98 5296.37,5563.41 5296.37,5878.25 5296.37,5920.64 ccw(c5281.74,5920.64) 5281.74,5935.26 5278.86,5935.26 cw(c5278.86,5940.39) 5273.73,5940.39 5273.73,5950.64 cw(c5278.86,5950.64) 5278.86,5955.76 5281.74,5955.76 ccw(c5281.74,5970.39) 5296.37,5970.39 5296.37,6007.14 5296.37,6060.57 5301.46,6065.66 CON13.20@5301.46,6089.26
eDP_A_LANE0_P/LVDS_D_LANE0_P: CON13.21 CON16.63 | length 2602.7
  Top Layer w4: CON16.63@4478.35,3851.92 4478.35,3898.75 4483.44,3903.84 4483.44,4763.92 5286.87,5567.35 5286.87,5878.25 5286.87,5920.64 ccw(c5281.74,5920.64) 5281.74,5925.76 5278.86,5925.76 cw(c5278.86,5940.39) 5264.23,5940.39 5264.23,5950.64 cw(c5278.86,5950.64) 5278.86,5965.26 5281.74,5965.26 ccw(c5281.74,5970.39) 5286.87,5970.39 5286.87,6007.14 5286.87,6060.15 5281.77,6065.24 CON13.21@5281.77,6089.26
eDP_A_LANE1_N/LVDS_D_LANE1_N: CON13.17 CON16.71 | length 2602.6
  Top Layer w4: CON16.71@4557.09,3851.92 4557.09,3898.95 4552.04,3904 4552.04,4755.62 5355.42,5559 5355.42,5806.01 5355.42,5812.76 ccw(c5340.8,5812.76) 5340.8,5827.39 5337.91,5827.39 cw(c5337.91,5832.51) 5332.78,5832.51 5332.78,5842.76 cw(c5337.91,5842.76) 5337.91,5847.89 5340.8,5847.89 ccw(c5340.8,5862.51) 5355.42,5862.51 5355.42,5895.35 5355.42,6059.36 5360.51,6064.46 CON13.17@5360.51,6089.26
eDP_A_LANE1_P/LVDS_D_LANE1_P: CON13.18 CON16.69 | length 2602.7
  Top Layer w4: CON16.69@4537.4,3851.92 4537.4,3898.75 4542.54,3903.89 4542.54,4759.56 5345.92,5562.93 5345.92,5806.01 5345.92,5812.76 ccw(c5340.8,5812.76) 5340.8,5817.89 5337.91,5817.89 cw(c5337.91,5832.51) 5323.28,5832.51 5323.28,5842.76 cw(c5337.91,5842.76) 5337.91,5857.39 5340.8,5857.39 ccw(c5340.8,5862.51) 5345.92,5862.51 5345.92,5895.35 5345.92,6059.76 5340.83,6064.85 CON13.18@5340.83,6089.26
eDP_A_LANE2_N/LVDS_D_LANE2_N: CON13.14 CON16.77 | length 2602.7
  Top Layer w4: CON16.77@4616.14,3851.92 4616.14,3898.95 4611.05,3904.05 4611.05,4731.13 5414.48,5534.56 5414.48,5918.48 5414.48,5925.23 ccw(c5399.85,5925.23) 5399.85,5939.86 5396.97,5939.86 cw(c5396.97,5944.98) 5391.84,5944.98 5391.84,5955.23 cw(c5396.97,5955.23) 5396.97,5960.36 5399.85,5960.36 ccw(c5399.85,5974.98) 5414.48,5974.98 5414.48,5999.64 5414.48,6059.94 5419.57,6065.03 CON13.14@5419.57,6089.26
eDP_A_LANE2_P/LVDS_D_LANE2_P: CON13.15 CON16.75 | length 2602.7
  Top Layer w4: CON16.75@4596.46,3851.92 4596.46,3898.75 4601.55,3903.84 4601.55,4735.07 5404.98,5538.49 5404.98,5918.48 5404.98,5925.23 ccw(c5399.85,5925.23) 5399.85,5930.36 5396.97,5930.36 cw(c5396.97,5944.98) 5382.34,5944.98 5382.34,5955.23 cw(c5396.97,5955.23) 5396.97,5969.86 5399.85,5969.86 ccw(c5399.85,5974.98) 5404.98,5974.98 5404.98,5999.64 5404.98,6060.01 5399.88,6065.11 CON13.15@5399.88,6089.26
eDP_A_LANE3_N/LVDS_D_LANE3_N: CON13.11 CON16.83 | length 2602.3
  Top Layer w4: CON16.83@4675.2,3851.92 4675.2,3898.95 4670.1,3904.05 4670.1,3936.14 4654.25,3952 4654.25,4688.1 5474.2,5508.06 5474.2,5969.78 5489.24,5984.83 5492.03,5987.61 5492.03,6015.48 5474.2,6033.31 5474.2,6060.94 5478.62,6065.37 CON13.11@5478.62,6089.26
eDP_A_LANE3_P/LVDS_D_LANE3_P: CON13.12 CON16.81 | length 2602.8
  Top Layer w4: CON16.81@4655.51,3851.92 4655.51,3898.75 4660.6,3903.84 4660.6,3932.2 4644.75,3948.06 4644.75,4692.04 5464.7,5511.99 5464.7,5973.72 5482.53,5991.54 5482.53,6011.55 5464.7,6029.37 5464.7,6059.36 5458.94,6065.12 CON13.12@5458.94,6089.26
eDP_B_AUX_N/LVDS_E_CLK_N: CON14.8 CON16.119 | length 2969.9
  Top Layer w4: CON16.119@5029.53,3851.92 5029.53,3898.01 5024.2,3903.33 5024.2,3940.89 5032.74,3949.42 5049.9,3949.42 5074.37,3924.96 5105.08,3924.96 5128.51,3948.39 5161.96,3948.39 5408.5,4194.93 5408.5,4762.07 6546,5899.56 6546,6068.43 6551.09,6073.53 CON14.8@6551.09,6090.59
eDP_B_AUX_P/LVDS_E_CLK_P: CON14.9 CON16.117 | length 2969.7
  Top Layer w4: CON16.117@5009.84,3851.92 5009.84,3898.65 5014.7,3903.51 5014.7,3944.82 5028.8,3958.92 5053.84,3958.92 5078.3,3934.46 5101.14,3934.46 5124.57,3957.89 5158.02,3957.89 5399,4198.87 5399,4766 6536.5,5903.5 6536.5,6068.77 6531.4,6073.86 CON14.9@6531.4,6090.59
eDP_B_LANE0_N/LVDS_E_LANE0_N: CON14.20 CON16.95 | length 2971.5
  Top Layer w4: CON16.95@4793.31,3851.92 4793.31,3898.95 4788.22,3904.05 4788.22,3948.39 4733.36,4003.25 4733.36,4229.67 4733.36,4255.1 cw(c4738.49,4255.1) 4738.49,4260.22 4753.67,4260.22 ccw(c4753.67,4274.85) 4768.29,4274.85 4768.29,4285.1 ccw(c4753.67,4285.1) 4753.67,4299.72 4738.49,4299.72 cw(c4738.49,4304.85) 4733.36,4304.85 4733.36,4311.6 4733.36,4366.74 4956.8,4590.18 4956.8,4653.68 6309.78,6006.66 6309.78,6068.14 6314.87,6073.23 CON14.20@6314.87,6090.59
eDP_B_LANE0_P/LVDS_E_LANE0_P: CON14.21 CON16.93 | length 2971.5
  Top Layer w4: CON16.93@4773.62,3851.92 4773.62,3898.75 4778.72,3903.84 4778.72,3944.46 4723.86,3999.31 4723.86,4229.67 4723.86,4255.1 cw(c4738.49,4255.1) 4738.49,4269.72 4753.67,4269.72 ccw(c4753.67,4274.85) 4758.79,4274.85 4758.79,4285.1 ccw(c4753.67,4285.1) 4753.67,4290.22 4738.49,4290.22 cw(c4738.49,4304.85) 4723.86,4304.85 4723.86,4311.6 4723.86,4370.67 4947.3,4594.11 4947.3,4657.61 6300.28,6010.59 6300.28,6068.73 6295.18,6073.82 CON14.21@6295.18,6090.59
eDP_B_LANE1_N/LVDS_E_LANE1_N: CON14.17 CON16.101 | length 2970.3
  Top Layer w4: CON16.101@4852.36,3851.92 4852.36,3898.95 4847.25,3904.06 4847.25,3931.44 4842.3,3936.39 4842.3,3959.8 4847.25,3964.75 4847.25,3992.49 4923.27,4068.51 5082.08,4068.51 5201.79,4188.22 5201.79,4827.23 6368.83,5994.27 6368.83,6067.53 6373.92,6072.62 CON14.17@6373.92,6090.59
eDP_B_LANE1_P/LVDS_E_LANE1_P: CON14.18 CON16.99 | length 2970.3
  Top Layer w4: CON16.99@4832.68,3851.92 4832.68,3898.75 4837.75,3903.83 4837.75,3927.5 4832.8,3932.45 4832.8,3963.73 4835.59,3966.51 4837.75,3968.68 4837.75,3996.43 4919.33,4078.01 5078.14,4078.01 5192.29,4192.16 5192.29,4508.12 5192.29,4831.16 6359.33,5998.2 6359.33,6068.77 6354.24,6073.86 CON14.18@6354.24,6090.59
eDP_B_LANE2_N/LVDS_E_LANE2_N: CON14.14 CON16.107 | length 2969.7
  Top Layer w4: CON16.107@4911.42,3851.92 4911.42,3898.95 4906.34,3904.03 4906.34,3981.31 4951.41,4026.38 5116.24,4026.38 5269.84,4179.99 5269.84,4800.37 6427.89,5958.41 6427.89,6068.81 6432.98,6073.9 CON14.14@6432.98,6090.59
eDP_B_LANE2_P/LVDS_E_LANE2_P: CON14.15 CON16.105 | length 2969.7
  Top Layer w4: CON16.105@4891.73,3851.92 4891.73,3898.75 4896.84,3903.86 4896.84,3985.25 4947.47,4035.88 5112.3,4035.88 5260.34,4183.92 5260.34,4804.3 6418.39,5962.34 6418.39,6068.77 6413.29,6073.86 CON14.15@6413.29,6090.59
eDP_B_LANE3_N/LVDS_E_LANE3_N: CON14.11 CON16.113 | length 2970.2
  Top Layer w4: CON16.113@4970.47,3851.92 4970.47,3898.01 4965.52,3902.96 4965.52,3973.96 4979.78,3988.22 5145.63,3988.22 5339.55,4182.14 5339.55,4777.87 6486.94,5925.26 6486.94,6068.43 6492.03,6073.53 CON14.11@6492.03,6090.59
eDP_B_LANE3_P/LVDS_E_LANE3_P: CON14.12 CON16.111 | length 2970.3
  Top Layer w4: CON16.111@4950.79,3851.92 4950.79,3898.65 4956.02,3903.88 4956.02,3977.9 4975.85,3997.72 5141.69,3997.72 5330.05,4186.08 5330.05,4781.81 6477.44,5929.2 6477.44,6068.77 6472.35,6073.86 CON14.12@6472.35,6090.59
eMMC_VDDM: C360.1 C361.1 U49.C2 | length 139
  Top Layer w3: v1@4209.55,4914.04 v1(4209.55,4914.52) v1@4208.72,4915.34 ; v1@4208.72,4915.34 4218.52,4925.13 4218.52,4942.34 U49.C2@4208.72,4952.14 4199.06,4942.48 4199.06,4925 v1@4208.72,4915.34
  Bottom Layer w10: v1@4209.55,4914.04 4207.98,4912.47 C361.1@4207.98,4893.08 4208.13,4892.93 C360.1@4233.97,4892.93
ENET0_LED0: Q5.1 R93.2 R108.1 U10.47 | length 1268.2
  Top Layer w4: Q5.1@832,2982.7 832,2985.07 861.84,3014.9 887.38,3014.9 962.48,3090 1167.45,3090 1181.11,3103.66 v1(1181.11,3103.88) ; v1(1231.54,3715.17) 1233.97,3717.6 1251.7,3717.6 1251.7,3711.66 1265.73,3697.63 1265.73,3667.61 1260.26,3662.14 R108.1@1250.74,3662.14 1250.74,3649.05 1276.96,3622.83 U10.47@1276.96,3610.53
  Bottom Layer w4: v1(1181.11,3103.88) 1169.27,3115.71 1169.27,3160.96 1100.39,3229.84 1100.39,3587.21 1180.42,3667.25 1193.37,3667.25 1203.93,3677.8 1203.93,3694.56 1224.54,3715.17 v1(1231.54,3715.17)
ENET0_LED1: R94.2 R107.1 U10.46 | length 133.1
  Top Layer w4: R94.2@1281.53,3718.64 1295.79,3704.39 1295.79,3666.33 1291.61,3662.14 R107.1@1280.84,3662.14 1280.84,3642.45 1296.64,3626.65 U10.46@1296.64,3610.53
ENET0_LED2: Q6.1 R95.2 R106.1 U10.45 | length 757.5
  Top Layer w4: Q6.1@831.58,4037.11 917.49,4037.11 1165.95,3788.66 1257.91,3788.66 1297.69,3748.88 1297.69,3724.08 1302.87,3718.9 1311.57,3718.9 R95.2@1313.17,3718.9 1318.76,3718.9 1326.03,3711.63 1326.03,3670.72 1317.45,3662.14 R106.1@1310.75,3662.14 1316.33,3656.57 U10.45@1316.33,3610.53
ENET0_TRXA_N: CON2.3 D7.2 D7.9 U10.2 | length 599.9
  Top Layer w4: CON2.3@790,3615 760.8,3615 747.7,3628.09 747.7,3641.3 765.88,3659.47 842.16,3659.47 886.93,3614.7 906.22,3614.7 911.31,3609.61 D7.2@921.3,3609.61 930.3,3609.61 935.39,3614.7 942.96,3614.7 948.05,3609.61 D7.9@957.3,3609.61 967.48,3609.61 972.57,3614.7 1015.02,3614.7 1059.75,3569.98 1220.22,3569.98 1224.95,3565.25 U10.2@1231.68,3565.25
ENET0_TRXA_P: CON2.2 D7.1 D7.10 U10.1 | length 603.7
  Top Layer w4: CON2.2@690,3665 705.23,3649.76 742.74,3649.76 761.95,3668.97 846.09,3668.97 890.86,3624.2 906.82,3624.2 911.91,3629.29 D7.1@921.3,3629.29 930.24,3629.29 935.33,3624.2 943.21,3624.2 948.3,3629.29 D7.10@957.3,3629.29 966.91,3629.29 972,3624.2 1018.96,3624.2 1063.68,3579.48 1219.86,3579.48 1225.32,3584.94 U10.1@1231.68,3584.94
ENET0_TRXB_N: CON2.5 D7.5 D7.6 U10.5 | length 581.1
  Top Layer w4: CON2.5@790,3515 757.18,3515 748.13,3524.05 748.13,3540.98 762.78,3555.64 906.03,3555.64 911.12,3550.55 D7.5@921.3,3550.55 930.3,3550.55 935.39,3555.64 942.96,3555.64 948.05,3550.55 D7.6@957.3,3550.55 967.48,3550.55 972.57,3555.64 984.61,3555.64 1028.41,3511.84 1221.09,3511.84 1226.73,3506.2 U10.5@1231.68,3506.2
ENET0_TRXB_P: CON2.4 D7.4 D7.7 U10.4 | length 584.5
  Top Layer w4: CON2.4@690,3565 707.29,3547.7 741.41,3547.7 758.85,3565.14 906.47,3565.14 911.56,3570.23 D7.4@921.3,3570.23 930.24,3570.23 935.33,3565.14 943.21,3565.14 948.3,3570.23 D7.7@957.3,3570.23 965.71,3570.23 970.8,3565.14 988.54,3565.14 1032.35,3521.34 1220.75,3521.34 1225.29,3525.88 U10.4@1231.68,3525.88
ENET0_TRXC_N: CON2.7 D6.2 D6.9 U10.8 | length 595.1
  Top Layer w4: CON2.7@790,3419.84 760.8,3419.84 747.7,3432.94 747.7,3446.14 765.88,3464.32 842.16,3464.32 886.93,3419.55 906.22,3419.55 911.31,3414.46 D6.2@921.3,3414.46 930.3,3414.46 935.39,3419.55 942.96,3419.55 948.05,3414.46 D6.9@957.3,3414.46 962.39,3419.55 986.98,3419.55 1019.71,3452.28 1220.79,3452.28 1225.93,3447.14 U10.8@1231.68,3447.14
ENET0_TRXC_P: CON2.6 D6.1 D6.10 U10.7 | length 598.6
  Top Layer w4: CON2.6@690,3469.84 705.23,3454.61 742.74,3454.61 761.95,3473.82 846.09,3473.82 890.86,3429.05 906.82,3429.05 911.91,3434.14 D6.1@921.3,3434.14 930.24,3434.14 935.33,3429.05 943.21,3429.05 948.3,3434.14 D6.10@957.3,3434.14 962.39,3429.05 983.04,3429.05 1015.78,3461.78 1220.41,3461.78 1225.46,3466.83 U10.7@1231.68,3466.83
ENET0_TRXD_N: CON2.9 D6.5 D6.6 U10.11 | length 576.9
  Top Layer w4: CON2.9@790,3319.84 757.18,3319.84 748.13,3328.89 748.13,3345.83 762.78,3360.49 906.03,3360.49 911.12,3355.4 D6.5@921.3,3355.4 930.3,3355.4 935.39,3360.49 942.96,3360.49 948.05,3355.4 D6.6@957.3,3355.4 962.39,3360.49 1016.93,3360.49 1050.35,3393.9 1219.64,3393.9 1225.46,3388.09 U10.11@1231.68,3388.09
ENET0_TRXD_P: CON2.8 D6.4 D6.7 U10.10 | length 579.3
  Top Layer w4: CON2.8@690,3369.84 707.29,3352.55 741.41,3352.55 758.85,3369.99 906.47,3369.99 911.56,3375.08 D6.4@921.3,3375.08 930.24,3375.08 935.33,3369.99 943.21,3369.99 948.3,3375.08 D6.7@957.3,3375.08 962.39,3369.99 1013,3369.99 1046.42,3403.4 1219.64,3403.4 ; U10.10@1220.47,3403.4 1224.84,3407.77 U10.10@1231.68,3407.77
ENET1_LED0: Q7.1 R126.2 R141.1 U11.47 | length 1187.4
  Top Layer w4: Q7.1@835.95,4165.02 835.95,4166.47 v1(863.23,4193.76) ; R126.2@1255.64,4899.91 v1@1255.64,4884.46 ; R126.2@1255.64,4901.09 v1@1255.64,4884.46 ; U11.47@1280.9,4792.84 1280.9,4805.14 1254.68,4831.36 R141.1@1254.68,4844.46 1264.2,4844.46 1269.99,4850.25 1269.99,4875.13 1261.18,4883.94 v1(1255.12,4883.94) ; v1(1255.12,4883.94) v1@1255.64,4884.46 ; v1(1255.12,4883.94) v1@1255.64,4884.46
  Bottom Layer w4: v1(863.23,4193.76) 1105.94,4436.47 1105.94,4886.61 1161.07,4941.74 1191.54,4941.74 1250.39,4882.88 1254.06,4882.88 v1(1255.12,4883.94)
ENET1_LED1: R127.2 R140.1 U11.46 | length 137.8
  Top Layer w4: R127.2@1285.47,4900.96 1293.49,4900.96 1299.73,4894.72 1299.73,4848.64 1295.55,4844.46 R140.1@1284.79,4844.46 1284.78,4824.77 1300.58,4808.97 U11.46@1300.58,4792.84
ENET1_LED2: Q8.1 R128.2 R139.1 U11.45 | length 760.6
  Top Layer w4: Q8.1@833.77,5217.67 920.79,5217.67 1174.54,4963.92 1274.99,4963.92 1300.8,4938.11 1300.8,4906.87 1306.59,4901.09 R128.2@1316.62,4901.09 1320.37,4901.09 1329.71,4891.75 1329.71,4852.77 1321.39,4844.46 R139.1@1314.7,4844.46 1320.27,4838.89 U11.45@1320.27,4792.84
ENET1_TRXA_N: CON3.3 D11.2 D11.9 U11.2 | length 599.9
  Top Layer w4: CON3.3@793.94,4797.31 764.74,4797.31 751.65,4810.41 751.65,4823.61 769.82,4841.79 846.1,4841.79 890.87,4797.02 910.16,4797.02 915.25,4791.93 D11.2@925.24,4791.93 934.24,4791.93 939.33,4797.02 946.9,4797.02 951.99,4791.93 D11.9@961.24,4791.93 971.42,4791.93 976.51,4797.02 1018.97,4797.02 1063.69,4752.29 1224.17,4752.29 1228.89,4747.57 U11.2@1235.62,4747.57
ENET1_TRXA_P: CON3.2 D11.1 D11.10 U11.1 | length 603.7
  Top Layer w4: CON3.2@693.94,4847.31 709.17,4832.08 746.68,4832.08 765.89,4851.29 850.03,4851.29 894.8,4806.52 910.76,4806.52 915.85,4811.61 D11.1@925.24,4811.61 934.18,4811.61 939.27,4806.52 947.15,4806.52 952.24,4811.61 D11.10@961.24,4811.61 970.86,4811.61 975.95,4806.52 1022.9,4806.52 1067.62,4761.79 1223.8,4761.79 1229.26,4767.25 U11.1@1235.62,4767.25
ENET1_TRXB_N: CON3.5 D11.5 D11.6 U11.5 | length 581.1
  Top Layer w4: CON3.5@793.94,4697.31 761.12,4697.31 752.07,4706.36 752.07,4723.3 766.72,4737.96 909.97,4737.96 915.06,4732.87 D11.5@925.24,4732.87 934.24,4732.87 939.33,4737.96 946.9,4737.96 951.99,4732.87 D11.6@961.24,4732.87 971.42,4732.87 976.51,4737.96 988.55,4737.96 1032.35,4694.15 1225.03,4694.15 1230.67,4688.51 U11.5@1235.62,4688.51
ENET1_TRXB_P: CON3.4 D11.4 D11.7 U11.4 | length 584.5
  Top Layer w4: CON3.4@693.94,4747.31 711.24,4730.02 745.35,4730.02 762.79,4747.46 910.41,4747.46 915.5,4752.55 D11.4@925.24,4752.55 934.18,4752.55 939.27,4747.46 947.15,4747.46 952.24,4752.55 D11.7@961.24,4752.55 969.65,4752.55 974.74,4747.46 992.49,4747.46 1036.29,4703.65 1224.69,4703.65 1229.23,4708.2 U11.4@1235.62,4708.2
ENET1_TRXC_N: CON3.7 D10.2 D10.9 U11.8 | length 595.1
  Top Layer w4: CON3.7@793.94,4602.16 764.74,4602.16 751.65,4615.25 751.65,4628.46 769.82,4646.63 846.1,4646.63 890.87,4601.86 910.16,4601.86 915.25,4596.77 D10.2@925.24,4596.77 934.24,4596.77 939.33,4601.86 946.9,4601.86 951.99,4596.77 D10.9@961.24,4596.77 970.21,4596.77 975.3,4601.86 990.28,4601.86 1023.02,4634.59 1224.73,4634.59 1229.87,4629.46 U11.8@1235.62,4629.46
ENET1_TRXC_P: CON3.6 D10.1 D10.10 U11.7 | length 598.6
  Top Layer w4: CON3.6@693.94,4652.16 709.17,4636.92 746.68,4636.92 765.89,4656.13 850.03,4656.13 894.8,4611.36 910.76,4611.36 915.85,4616.45 D10.1@925.24,4616.45 934.18,4616.45 939.27,4611.36 947.15,4611.36 952.24,4616.45 D10.10@961.24,4616.45 970.46,4616.45 975.56,4611.36 986.35,4611.36 1019.08,4644.09 1224.35,4644.09 1229.4,4649.14 U11.7@1235.62,4649.14
ENET1_TRXD_N: CON3.9 D10.5 D10.6 U11.11 | length 576.9
  Top Layer w4: CON3.9@793.94,4502.16 761.12,4502.16 752.07,4511.21 752.07,4528.14 766.72,4542.8 909.97,4542.8 915.06,4537.71 D10.5@925.24,4537.71 934.24,4537.71 939.33,4542.8 946.9,4542.8 951.99,4537.71 D10.6@961.24,4537.71 969.39,4537.71 974.48,4542.8 1020.87,4542.8 1054.29,4576.22 1223.58,4576.22 1229.4,4570.4 U11.11@1235.62,4570.4
ENET1_TRXD_P: CON3.8 D10.4 D10.7 U11.10 | length 579.3
  Top Layer w4: CON3.8@693.94,4552.16 711.24,4534.86 745.35,4534.86 762.79,4552.3 910.41,4552.3 915.5,4557.39 D10.4@925.24,4557.39 934.18,4557.39 939.27,4552.3 947.15,4552.3 952.24,4557.39 D10.7@961.24,4557.39 970.23,4557.39 975.32,4552.3 1016.94,4552.3 1050.36,4585.72 1223.58,4585.72 ; U11.10@1224.41,4585.72 1228.78,4590.09 U11.10@1235.62,4590.09
ENET_1V0: C306.1 C307.1 C308.1 C309.1 FB16.1 FB18.1 L13.2 R231.1 TP24.1 | length 153.5
  Top Layer w12: C306.1@1287.64,4182.96 1288.34,4183.66 R231.1@1322.8,4183.66 ; v1(1382.33,4269.71) 1430.66,4269.71 1435.47,4264.9 L13.2@1435.47,4252.31
  Top Layer w20: FB18.1@1302.27,4137.63 1322.8,4158.15 R231.1@1322.8,4179.46
ETH0_VDDA_1V0: C134.2 C135.1 C136.1 C137.1 FB16.2 U10.6 U10.24 U10.31 U10.42 | length 1751
  Top Layer w10: v1(1206.13,3486.96) 1206.57,3486.51 U10.6@1231.68,3486.51 ; U10.42@1375.38,3610.53 1375.38,3628.85 v1(1387.16,3640.62) 1402.13,3655.59 C134.2@1402.13,3662.15 ; v1(1454,3305.15) 1454.39,3304.76 1473.37,3304.76 C136.1@1473.81,3305.19 U10.24@1473.81,3342.81 ; v1(1473.01,3492.91) 1479.4,3486.51 U10.31@1499.4,3486.51
  Top Layer w20: v1@1301.83,4058.15 FB16.2@1301.83,4077.84
  L3 w20: v1(1206.13,3486.96) 1221.97,3486.96 1251.23,3457.7 1402.1,3457.7 ; v1(1300.96,4057.28) 1172.13,4057.28 1106.95,3992.11 1106.95,3739.38 1186.47,3659.86 1367.92,3659.86 v1(1387.16,3640.62) 1357.26,3610.72 1357.26,3557.38 1378.14,3536.49 1445.07,3536.49 1473.01,3508.56 v1(1473.01,3492.91) 1437.3,3492.91 1402.1,3457.7 ; v1(1454,3305.15) 1426.56,3332.59 1426.56,3433.24 1402.1,3457.7
  Bottom Layer w10: v1(1206.13,3486.96) 1207.24,3485.85 C137.1@1235.03,3485.85 ; C135.1@1456.09,3492.99 1472.92,3492.99 v1(1473.01,3492.91)
ETH0_VDDA_2V5: C131.2 C132.1 C133.1 C141.2 C167.2 FB15.2 R81.1 R85.1 R114.1 R118.1 U10.3 U10.9 | length 3247.9
  Top Layer w10: R85.1@727.74,3061.03 727.74,3083.88 ; 728.19,3084.34 754.6,3110.74 1052,3110.74 1119.5,3178.23 FB15.2@1119.5,3186.56 ; R118.1@728.78,4242.61 728.78,4264.4 v1(729.37,4264.99) ; v1@880.46,4014.84 880.75,4014.55 R81.1@880.75,3994.26 905.54,3994.26 C141.2@905.68,3994.12 ; v1(884.99,5194.88) 884.69,5194.59 R114.1@884.69,5173.76 909.48,5173.76 C167.2@909.63,5173.62 ; v1(1205.03,3545.66) 1205.11,3545.57 U10.3@1231.68,3545.57 ; v1(1205.48,3427.66) 1205.69,3427.46 U10.9@1231.68,3427.46
  Top Layer w20: FB15.2@1119.5,3186.56 1119.5,3220.11 v1(1136.65,3237.26)
  L3 w20: v1(884.99,5194.88) 942.85,5137.03 942.85,4359.12 848.72,4264.99 v1(729.37,4264.99) 729.37,4165.93 v1(879.64,4015.66) 879.64,3845.56 1179.54,3545.66 v1(1205.03,3545.66)
  Bottom Layer w10: v1(1205.03,3545.66) 1206.29,3546.91 C132.1@1234.89,3546.91 ; v1(1205.48,3427.66) 1207.58,3429.77 1234.9,3429.77 1234.9,3404.43 C131.2@1234.94,3404.39
  Bottom Layer w20: v1(1136.65,3237.26) 1127.83,3246.08 1127.83,3423.48 ; v1(1205.03,3545.66) 1191,3545.66 1127.83,3482.49 1127.83,3423.48 ; v1(1205.48,3427.66) 1132.01,3427.66 1127.83,3423.48
ETH1_VDDA_1V0: C160.2 C161.1 C162.1 C163.1 FB18.2 U11.6 U11.24 U11.31 U11.42 | length 1413.1
  Top Layer w10: v1(1210.07,4669.27) 1210.51,4668.83 U11.6@1235.62,4668.83 ; U11.42@1379.32,4792.84 1379.32,4809.13 v1(1391.84,4821.64) 1406.07,4835.87 C162.1@1406.07,4844.47 ; v1(1456.8,4488.13) 1457.86,4487.07 1477.31,4487.07 C160.2@1477.75,4487.51 U11.24@1477.75,4525.13 ; v1(1477.85,4668.59) 1478.09,4668.83 U11.31@1503.34,4668.83
  Top Layer w20: v1(1238.23,4140.71) 1238.43,4140.51 FB18.2@1267.27,4140.51
  L3 w20: v1(1210.07,4669.27) 1234.37,4669.27 1270.14,4633.51 1359.14,4633.51 1410.18,4684.55 ; v1(1238.23,4140.71) 1238.23,4192.34 1375.19,4329.31 1375.19,4398.61 1396.23,4419.65 1444.42,4419.65 1465.09,4440.32 1465.09,4479.85 v1(1456.8,4488.13) 1431.52,4513.41 1431.52,4622.26 v1(1477.85,4668.59) 1461.9,4684.55 1410.18,4684.55 ; v1(1391.84,4821.64) 1364.58,4794.38 1364.58,4730.15 1410.18,4684.55
  Bottom Layer w10: v1(1210.07,4669.27) 1211.18,4668.16 C163.1@1238.84,4668.16 C163.1@1238.97,4668.16 ; C161.1@1460.03,4675.31 1471.14,4675.31 v1(1477.85,4668.59)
